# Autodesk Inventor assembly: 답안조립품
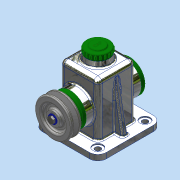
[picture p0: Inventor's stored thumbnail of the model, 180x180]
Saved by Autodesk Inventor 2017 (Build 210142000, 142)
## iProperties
Part Number: 답안조립품
Material: 일반
Document SubType Name: Assembly
Designer: MRC
Author: MRC
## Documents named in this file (14)
- C:\Users\MRC\Desktop\700907V1003\답안조립품.iam
- C:\Users\MRC\Desktop\700907V1003\본체.ipt
- C:\Users\MRC\Desktop\700907V1003\V-벨트풀리.ipt
- C:\Users\MRC\Desktop\700907V1003\뒤커버.ipt
- C:\Users\MRC\Desktop\700907V1003\멈춤링 15 x 1.ipt
- C:\Users\MRC\Desktop\700907V1003\베어링 15 x 35 x 11.ipt
- C:\Users\MRC\Desktop\700907V1003\볼트 M4 x 10.ipt
- C:\Users\MRC\Desktop\700907V1003\볼트 M6 x 12.ipt
- C:\Users\MRC\Desktop\700907V1003\상부캡.ipt
- C:\Users\MRC\Desktop\700907V1003\앞커버.ipt
- C:\Users\MRC\Desktop\700907V1003\오일실 15 25 7.ipt
- C:\Users\MRC\Desktop\700907V1003\와셔.ipt
- C:\Users\MRC\Desktop\700907V1003\축.ipt
- C:\Users\MRC\Desktop\700907V1003\키 5 x 5 x 14.ipt
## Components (1 placed, 1 different names)
1. V-벨트풀리:1
